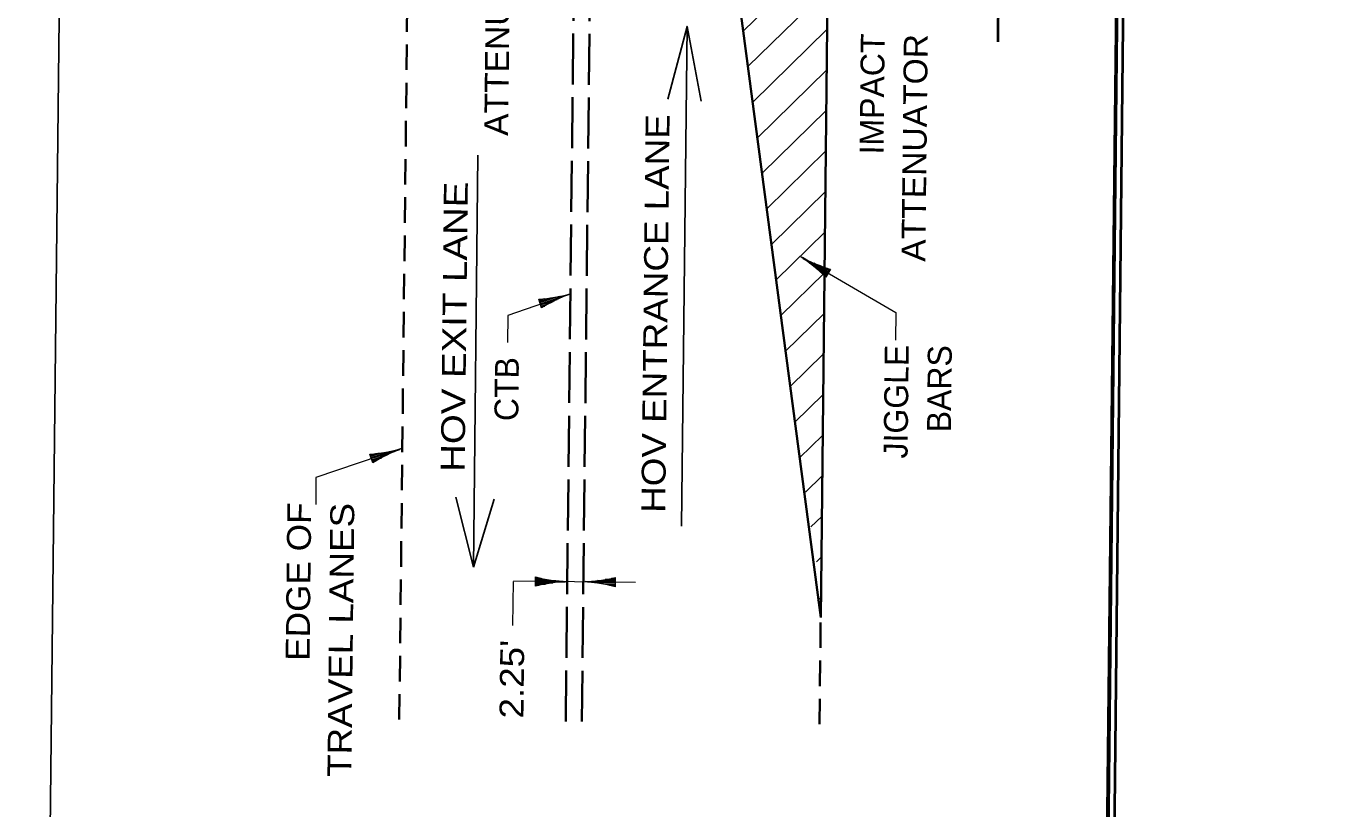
# Model space of a CAD drawing. Extents: x 2356576 to 2377878, y 6966390 to 6990634.
# Drawn here: x 2366073 to 2367164, y 6973821 to 6974475 of the extents above; entities that cross this region are included whole.
import ezdxf
from ezdxf.enums import TextEntityAlignment as Align

# ---------------------------------------------------------------- set-up
doc = ezdxf.new("R2010")
doc.units = 0
doc.header["$LTSCALE"] = 7.1
doc.linetypes.add('LONG_DASHED', pattern=[7.5, 6, -1.5])
doc.linetypes.add('MEDIUM_DASHED', pattern=[4.5, 3, -1.5])
doc.layers.add('19', color=7, linetype='Continuous', lineweight=13)
doc.layers.add('8', color=7, linetype='Continuous', lineweight=13)

msp = doc.modelspace()

# ---------------------------------------------------------------- linework, layer by layer
at = {"layer": '19', "lineweight": 35}
for p, q in [((2366737.734, 6973980.518), (2366756.652, 6975684.12)), ((2366669.944, 6974494.146), (2366737.736, 6973980.506))]:
    msp.add_line(p, q, dxfattribs=at)
at = {"layer": '19', "lineweight": 40}
msp.add_line((2366886.132, 6974461.668), (2366894.232, 6975191.256), dxfattribs=at)
at = {"layer": '19', "linetype": 'LONG_DASHED', "lineweight": 35}
for p, q in [((2366524.464, 6973893.65), (2366533.082, 6974669.804)), ((2366537.964, 6973893.5), (2366546.582, 6974669.654))]:
    msp.add_line(p, q, dxfattribs=at)
at = {"layer": '19', "linetype": 'MEDIUM_DASHED', "lineweight": 35}
for p, q in [((2366385.32, 6973895.196), (2366392.98, 6974584.292)), ((2366736.746, 6973891.292), (2366737.736, 6973980.506))]:
    msp.add_line(p, q, dxfattribs=at)
at = {"layer": '19'}
for p, q in [((2366673.018, 6974470.856), (2366743.95, 6974540.23)), ((2366676.942, 6974441.126), (2366743.574, 6974506.29)), ((2366680.866, 6974411.396), (2366743.198, 6974472.364)), ((2366684.79, 6974381.666), (2366742.82, 6974438.418)), ((2366688.712, 6974351.942), (2366742.444, 6974404.492)), ((2366692.638, 6974322.206), (2366742.066, 6974370.548)), ((2366696.56, 6974292.482), (2366741.69, 6974336.62)), ((2366700.484, 6974262.748), (2366741.312, 6974302.684)), ((2366744, 6974268.52), (2366722.42, 6974281.394)), ((2366743.488, 6974267.664), (2366728.698, 6974276.484)), ((2366744.51, 6974269.38), (2366731.888, 6974276.91)), ((2366742.974, 6974266.804), (2366734.624, 6974271.784)), ((2366745.022, 6974270.238), (2366737.678, 6974274.62)), ((2366745.894, 6974271.7), (2366741.97, 6974265.12)), ((2366745.534, 6974271.098), (2366742.814, 6974272.722)), ((2366704.408, 6974233.018), (2366740.936, 6974268.742)), ((2366742.462, 6974265.944), (2366738.374, 6974268.384)), ((2366528.432, 6974251.122), (2366475.992, 6974232.94)), ((2366502.52, 6974244.728), (2366511.774, 6974247.714)), ((2366502.83, 6974243.776), (2366519.218, 6974249.062)), ((2366503.136, 6974242.826), (2366527.048, 6974250.54)), ((2366504.272, 6974239.302), (2366501.922, 6974246.594)), ((2366502.212, 6974245.68), (2366506.746, 6974247.142)), ((2366503.444, 6974241.874), (2366517.432, 6974246.386)), ((2366503.748, 6974240.922), (2366511.89, 6974243.546)), ((2366504.058, 6974239.97), (2366507.072, 6974240.942)), ((2366475.992, 6974232.94), (2366475.74, 6974210.464)), ((2366708.332, 6974203.286), (2366740.558, 6974234.802)), ((2366712.256, 6974173.556), (2366740.184, 6974200.87)), ((2366716.178, 6974143.826), (2366739.806, 6974166.93)), ((2366720.106, 6974114.098), (2366739.428, 6974132.998)), ((2366387.224, 6974121.728), (2366315.65, 6974097.572)), ((2366363.062, 6974109.908), (2366360.712, 6974117.2)), ((2366361.004, 6974116.286), (2366365.536, 6974117.748)), ((2366361.31, 6974115.334), (2366370.564, 6974118.32)), ((2366361.618, 6974114.382), (2366378.008, 6974119.668)), ((2366361.926, 6974113.432), (2366385.838, 6974121.146)), ((2366362.236, 6974112.48), (2366376.22, 6974116.992)), ((2366362.538, 6974111.528), (2366370.678, 6974114.152)), ((2366362.848, 6974110.576), (2366365.862, 6974111.548)), ((2366315.65, 6974097.572), (2366315.402, 6974075.096)), ((2366725.002, 6974085.326), (2366739.052, 6974099.068)), ((2366729.626, 6974056.278), (2366738.674, 6974065.13)), ((2366734.25, 6974027.224), (2366738.298, 6974031.184)), ((2366480.382, 6973973.826), (2366480.794, 6974010.68)), ((2366480.794, 6974011.104), (2366582.832, 6974009.97)), ((2366499.138, 6974013.474), (2366503.9, 6974013.474)), ((2366499.138, 6974012.474), (2366508.864, 6974012.474)), ((2366499.138, 6974010.476), (2366524.266, 6974010.476)), ((2366499.138, 6974008.474), (2366507.696, 6974008.472)), ((2366499.142, 6974006.772), (2366499.14, 6974014.434)), ((2366499.142, 6974011.474), (2366516.358, 6974011.472)), ((2366499.142, 6974007.474), (2366502.31, 6974007.474)), ((2366499.144, 6974009.474), (2366513.838, 6974009.474)), ((2366565.884, 6974010.262), (2366540.76, 6974010.566)), ((2366565.874, 6974009.264), (2366548.654, 6974009.474)), ((2366565.896, 6974011.262), (2366551.2, 6974011.44)), ((2366565.86, 6974008.262), (2366556.138, 6974008.38)), ((2366565.91, 6974012.262), (2366557.36, 6974012.368)), ((2366565.922, 6974013.262), (2366562.752, 6974013.302)), ((2366565.93, 6974013.964), (2366565.836, 6974006.304)), ((2366565.852, 6974007.262), (2366561.09, 6974007.32)), ((2366734.94, 6973994.324), (2366737.918, 6973997.238))]:
    msp.add_line(p, q, dxfattribs=at)
at = {"layer": '19', "lineweight": 25}
for p, q in [((2366625.97, 6974474.672), (2366610.01, 6974413.764)), ((2366447.292, 6974022.674), (2366451.116, 6974366.936)), ((2366447.292, 6974022.674), (2366432.66, 6974081.146)), ((2366447.292, 6974022.674), (2366464.594, 6974079.402))]:
    msp.add_line(p, q, dxfattribs=at)
at = {"layer": '19', "lineweight": 40}
msp.add_lwpolyline([(2363758.773, 6990629.355), (2367158.576, 6990592.767), (2366922.891, 6968646.236), (2363523.088, 6968682.826)], close=True, dxfattribs=at)
at = {"layer": '19', "lineweight": 25}
msp.add_lwpolyline([(2366974.866, 6973617.03), (2367000.838, 6975955.59), (2366117.376, 6975965.402), (2366091.406, 6973626.842)], close=True, dxfattribs=at)
msp.add_lwpolyline([(2366621.328, 6974056.838), (2366625.97, 6974474.672), (2366637.778, 6974412.068)], dxfattribs=at)
at = {"layer": '19'}
msp.add_lwpolyline([(2366722.994, 6974280.734), (2366800.618, 6974235.486), (2366800.364, 6974212.418)], dxfattribs=at)
for centre, start, end in [((2366641.021, 6974161.835), 45.65522, 56.34127), ((2366788.808, 6974409.601), 242.02838, 252.71443), ((2366490.962, 6974390.602), 274.35136, 285.03741), ((2366579.541, 6974116.043), 110.72452, 121.41057), ((2366349.752, 6974261.208), 274.35136, 285.03741), ((2366438.331, 6973986.649), 110.72452, 121.41057), ((2366532.923, 6974154.852), 256.47239, 267.15844), ((2366532.933, 6973866.358), 92.84556, 103.53161), ((2366533.845, 6974154.778), 272.14997, 282.83602), ((2366530.353, 6973866.305), 75.77681, 86.46286)]:
    msp.add_arc(centre, 144.425, start, end, dxfattribs=at)
at = {"layer": '8', "lineweight": 35}
for p, q in [((2366737.734, 6973980.518), (2366756.652, 6975684.12)), ((2366669.944, 6974494.146), (2366737.736, 6973980.506))]:
    msp.add_line(p, q, dxfattribs=at)
at = {"layer": '8', "lineweight": 40}
msp.add_line((2366886.132, 6974461.668), (2366894.232, 6975191.256), dxfattribs=at)
at = {"layer": '8', "linetype": 'LONG_DASHED', "lineweight": 35}
for p, q in [((2366524.464, 6973893.65), (2366533.082, 6974669.804)), ((2366537.964, 6973893.5), (2366546.582, 6974669.654))]:
    msp.add_line(p, q, dxfattribs=at)
at = {"layer": '8', "linetype": 'MEDIUM_DASHED', "lineweight": 35}
for p, q in [((2366385.32, 6973895.196), (2366392.98, 6974584.292)), ((2366736.746, 6973891.292), (2366737.736, 6973980.506))]:
    msp.add_line(p, q, dxfattribs=at)
at = {"layer": '8'}
for p, q in [((2366673.018, 6974470.856), (2366743.95, 6974540.23)), ((2366676.942, 6974441.126), (2366743.574, 6974506.29)), ((2366680.866, 6974411.396), (2366743.198, 6974472.364)), ((2366684.79, 6974381.666), (2366742.82, 6974438.418)), ((2366688.712, 6974351.942), (2366742.444, 6974404.492)), ((2366692.638, 6974322.206), (2366742.066, 6974370.548)), ((2366696.56, 6974292.482), (2366741.69, 6974336.62)), ((2366700.484, 6974262.748), (2366741.312, 6974302.684)), ((2366744, 6974268.52), (2366722.42, 6974281.394)), ((2366743.488, 6974267.664), (2366728.698, 6974276.484)), ((2366744.51, 6974269.38), (2366731.888, 6974276.91)), ((2366742.974, 6974266.804), (2366734.624, 6974271.784)), ((2366745.022, 6974270.238), (2366737.678, 6974274.62)), ((2366745.894, 6974271.7), (2366741.97, 6974265.12)), ((2366745.534, 6974271.098), (2366742.814, 6974272.722)), ((2366704.408, 6974233.018), (2366740.936, 6974268.742)), ((2366742.462, 6974265.944), (2366738.374, 6974268.384)), ((2366528.432, 6974251.122), (2366475.992, 6974232.94)), ((2366502.52, 6974244.728), (2366511.774, 6974247.714)), ((2366502.83, 6974243.776), (2366519.218, 6974249.062)), ((2366503.136, 6974242.826), (2366527.048, 6974250.54)), ((2366504.272, 6974239.302), (2366501.922, 6974246.594)), ((2366502.212, 6974245.68), (2366506.746, 6974247.142)), ((2366503.444, 6974241.874), (2366517.432, 6974246.386)), ((2366503.748, 6974240.922), (2366511.89, 6974243.546)), ((2366504.058, 6974239.97), (2366507.072, 6974240.942)), ((2366475.992, 6974232.94), (2366475.74, 6974210.464)), ((2366708.332, 6974203.286), (2366740.558, 6974234.802)), ((2366712.256, 6974173.556), (2366740.184, 6974200.87)), ((2366716.178, 6974143.826), (2366739.806, 6974166.93)), ((2366720.106, 6974114.098), (2366739.428, 6974132.998)), ((2366387.224, 6974121.728), (2366315.65, 6974097.572)), ((2366363.062, 6974109.908), (2366360.712, 6974117.2)), ((2366361.004, 6974116.286), (2366365.536, 6974117.748)), ((2366361.31, 6974115.334), (2366370.564, 6974118.32)), ((2366361.618, 6974114.382), (2366378.008, 6974119.668)), ((2366361.926, 6974113.432), (2366385.838, 6974121.146)), ((2366362.236, 6974112.48), (2366376.22, 6974116.992)), ((2366362.538, 6974111.528), (2366370.678, 6974114.152)), ((2366362.848, 6974110.576), (2366365.862, 6974111.548)), ((2366315.65, 6974097.572), (2366315.402, 6974075.096)), ((2366725.002, 6974085.326), (2366739.052, 6974099.068)), ((2366729.626, 6974056.278), (2366738.674, 6974065.13)), ((2366734.25, 6974027.224), (2366738.298, 6974031.184)), ((2366480.382, 6973973.826), (2366480.794, 6974010.68)), ((2366480.794, 6974011.104), (2366582.832, 6974009.97)), ((2366499.138, 6974013.474), (2366503.9, 6974013.474)), ((2366499.138, 6974012.474), (2366508.864, 6974012.474)), ((2366499.138, 6974010.476), (2366524.266, 6974010.476)), ((2366499.138, 6974008.474), (2366507.696, 6974008.472)), ((2366499.142, 6974006.772), (2366499.14, 6974014.434)), ((2366499.142, 6974011.474), (2366516.358, 6974011.472)), ((2366499.142, 6974007.474), (2366502.31, 6974007.474)), ((2366499.144, 6974009.474), (2366513.838, 6974009.474)), ((2366565.884, 6974010.262), (2366540.76, 6974010.566)), ((2366565.874, 6974009.264), (2366548.654, 6974009.474)), ((2366565.896, 6974011.262), (2366551.2, 6974011.44)), ((2366565.86, 6974008.262), (2366556.138, 6974008.38)), ((2366565.91, 6974012.262), (2366557.36, 6974012.368)), ((2366565.922, 6974013.262), (2366562.752, 6974013.302)), ((2366565.93, 6974013.964), (2366565.836, 6974006.304)), ((2366565.852, 6974007.262), (2366561.09, 6974007.32)), ((2366734.94, 6973994.324), (2366737.918, 6973997.238))]:
    msp.add_line(p, q, dxfattribs=at)
at = {"layer": '8', "lineweight": 25}
for p, q in [((2366625.97, 6974474.672), (2366610.01, 6974413.764)), ((2366447.292, 6974022.674), (2366451.116, 6974366.936)), ((2366447.292, 6974022.674), (2366432.66, 6974081.146)), ((2366447.292, 6974022.674), (2366464.594, 6974079.402))]:
    msp.add_line(p, q, dxfattribs=at)
at = {"layer": '8', "lineweight": 40}
for points in [[(2363753.827, 6990634.409), (2367163.63, 6990597.713), (2366927.837, 6968641.182), (2363518.034, 6968677.88)], [(2363758.773, 6990629.355), (2367158.576, 6990592.767), (2366922.891, 6968646.236), (2363523.088, 6968682.826)]]:
    msp.add_lwpolyline(points, close=True, dxfattribs=at)
at = {"layer": '8', "lineweight": 25}
msp.add_lwpolyline([(2366974.866, 6973617.03), (2367000.838, 6975955.59), (2366117.376, 6975965.402), (2366091.406, 6973626.842)], close=True, dxfattribs=at)
msp.add_lwpolyline([(2366621.328, 6974056.838), (2366625.97, 6974474.672), (2366637.778, 6974412.068)], dxfattribs=at)
at = {"layer": '8'}
msp.add_lwpolyline([(2366722.994, 6974280.734), (2366800.618, 6974235.486), (2366800.364, 6974212.418)], dxfattribs=at)
for centre, start, end in [((2366641.021, 6974161.835), 45.65522, 56.34127), ((2366788.808, 6974409.601), 242.02838, 252.71443), ((2366490.962, 6974390.602), 274.35136, 285.03741), ((2366579.541, 6974116.043), 110.72452, 121.41057), ((2366349.752, 6974261.208), 274.35136, 285.03741), ((2366438.331, 6973986.649), 110.72452, 121.41057), ((2366532.923, 6974154.852), 256.47239, 267.15844), ((2366532.933, 6973866.358), 92.84556, 103.53161), ((2366533.845, 6974154.778), 272.14997, 282.83602), ((2366530.353, 6973866.305), 75.77681, 86.46286)]:
    msp.add_arc(centre, 144.425, start, end, dxfattribs=at)

# ---------------------------------------------------------------- texts
at = {"layer": '19'}
for s, width, p in [('ATTENUATOR', 1.05, (2366478.422, 6974573.427)), ('ATTENUATOR', 1.05, (2366827.358, 6974468.225)), ('HOV ENTRANCE LANE', 1.15, (2366611.402, 6974401.206)), ('HOV EXIT LANE', 1.2, (2366442.676, 6974344.769)), ('EDGE OF', 1.1, (2366311.721, 6974076.629)), ('TRAVEL LANES', 1.15, (2366347.72, 6974076.233))]:
    msp.add_text(s, height=20, rotation=89.364, dxfattribs=dict(at, width=width)).set_placement(p, align=Align.RIGHT)
for s, p in [('IMPACT', (2366791.362, 6974468.623)), ('JIGGLE', (2366811.416, 6974208.503)), ('BARS', (2366847.413, 6974208.105)), ('CTB', (2366485.404, 6974198.166))]:
    msp.add_text(s, height=20, rotation=89.364, dxfattribs=at).set_placement(p, align=Align.RIGHT)
at = {"layer": '19', "width": 1.15}
msp.add_text("2.25'", height=20, rotation=89.364, dxfattribs=at).set_placement((2366489.118, 6973896.01))
at = {"layer": '8'}
for s, width, p in [('ATTENUATOR', 1.05, (2366478.422, 6974573.427)), ('ATTENUATOR', 1.05, (2366827.358, 6974468.225)), ('HOV ENTRANCE LANE', 1.15, (2366611.402, 6974401.206)), ('HOV EXIT LANE', 1.2, (2366442.676, 6974344.769)), ('EDGE OF', 1.1, (2366311.721, 6974076.629)), ('TRAVEL LANES', 1.15, (2366347.72, 6974076.233))]:
    msp.add_text(s, height=20, rotation=89.364, dxfattribs=dict(at, width=width)).set_placement(p, align=Align.RIGHT)
for s, p in [('IMPACT', (2366791.362, 6974468.623)), ('JIGGLE', (2366811.416, 6974208.503)), ('BARS', (2366847.413, 6974208.105)), ('CTB', (2366485.404, 6974198.166))]:
    msp.add_text(s, height=20, rotation=89.364, dxfattribs=at).set_placement(p, align=Align.RIGHT)
at = {"layer": '8', "width": 1.15}
msp.add_text("2.25'", height=20, rotation=89.364, dxfattribs=at).set_placement((2366489.118, 6973896.01))

doc.saveas('drawing.dxf')
